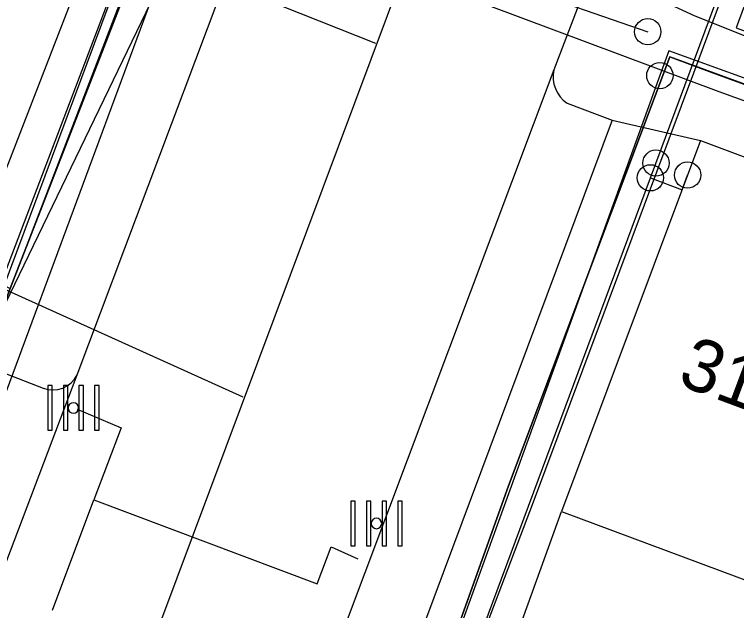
# Model space of a CAD drawing. Extents: x 192672 to 192910, y 446344 to 446512.
# Drawn here: x 192727.4 to 192741.13, y 446369.57 to 446380.91 of the extents above; entities that cross this region are included whole.
import ezdxf

# ---------------------------------------------------------------- set-up
doc = ezdxf.new("R2010")
doc.units = 0
for name, color, linetype in [('( Toegevoegd 29-11-2021 14_41_42) wegdeel vlak', 7, 'Continuous'), ('B-OI-KL-BUISLEIDING_OLIEGASCHEMICALIEN_GASLAGEDRUK-G', 7, 'Continuous'), ('B-OI-KL-DATA-G', 7, 'Continuous'), ('B-OI-KL-DATA_GTWP-S', 7, 'Continuous'), ('B-OI-KL-DATA_KABELBED-G', 7, 'Continuous'), ('B-OI-KL-DATA_MOF-S', 7, 'Continuous'), ('B-OI-KL-ET_LS-G', 7, 'Continuous'), ('B-OI-KL-GAS_LD_EINDKAP-S', 7, 'Continuous'), ('B-OI-KL-GAS_LD_OVERGANGSSTUK-S', 7, 'Continuous'), ('B-OI-KL-WATER-G', 7, 'Continuous'), ('B-OI-RI-RIOOLVRIJVERVAL-G', 7, 'Continuous'), ('Default', 7, 'Continuous'), ('huisnummerreeks BGT', 7, 'Continuous'), ('kant open verharding', 7, 'Continuous'), ('kant verharding', 7, 'Continuous'), ('kolk', 7, 'Continuous'), ('pand op maaiveld vlak', 7, 'Continuous')]:
    doc.layers.add(name, color=color, linetype=linetype)

# ---------------------------------------------------------------- blocks, each defined once
blk = doc.blocks.new('B-OI-KL-GAS_LD_EINDKAP-S')
at = {"layer": 'Default'}
blk.add_circle((0, 0), 0.25, dxfattribs=at)
blk = doc.blocks.new('B-OI-KL-GAS_LD_OVERGANGSSTUK-S')
at = {"layer": 'Default'}
blk.add_circle((0, 0), 0.25, dxfattribs=at)
blk = doc.blocks.new('B-OI-KL-DATA_GTWP-S')
at = {"layer": 'Default'}
blk.add_circle((0, 0), 0.25, dxfattribs=at)
blk = doc.blocks.new('B-OI-KL-DATA_MOF-S')
at = {"layer": 'Default'}
blk.add_circle((0, 0), 0.25, dxfattribs=at)

msp = doc.modelspace()

# ---------------------------------------------------------------- linework, layer by layer
at = {"layer": '( Toegevoegd 29-11-2021 14_41_42) wegdeel vlak'}
for p, q in [((192741.229, 446389.304), (192737.657, 446379.855)), ((192738.766, 446378.901), (192740.444, 446378.51)), ((192734.872, 446363.349), (192737.803, 446371.456))]:
    msp.add_line(p, q, dxfattribs=at)
msp.add_lwpolyline([(192744.875, 446390.822), (192741.123, 446380.652), (192757.478, 446374.617), (192757.644, 446375.067)], dxfattribs=at)
at = {"layer": 'B-OI-KL-BUISLEIDING_OLIEGASCHEMICALIEN_GASLAGEDRUK-G'}
for points in [[(192716.663, 446345.556), (192724.878, 446367.369), (192730.944, 446383.739), (192732.424, 446387.662), (192733.825, 446391.479)], [(192731.739, 446383.247), (192739.441, 446380.581)], [(192742.155, 446379.378), (192739.841, 446380.217), (192739.671, 446379.747)], [(192739.671, 446379.747), (192730.49, 446354.362), (192728.26, 446348.959), (192726.987, 446345.556)]]:
    msp.add_lwpolyline(points, dxfattribs=at)
at = {"layer": 'B-OI-KL-DATA-G'}
for points in [[(192768.74, 446486.807), (192749.794, 446435.599), (192742.072, 446415.039), (192739.06, 446406.841), (192738.917, 446406.249), (192738.75, 446405.758), (192738.438, 446405.088), (192738.002, 446404.406), (192737.543, 446403.858), (192737.067, 446403.408), (192736.56, 446403.025), (192736.06, 446402.723), (192733.684, 446396.245), (192734.518, 446394.712), (192730.316, 446383.423), (192727.316, 446375.697), (192722.899, 446364.033), (192722.458, 446362.715), (192718.077, 446351.086), (192716.68, 446347.404), (192715.968, 446345.556)], [(192768.74, 446486.807), (192749.794, 446435.599), (192742.072, 446415.039), (192739.06, 446406.841), (192738.917, 446406.249), (192738.75, 446405.758), (192738.438, 446405.088), (192738.002, 446404.406), (192737.543, 446403.858), (192737.067, 446403.408), (192736.56, 446403.025), (192736.06, 446402.723), (192733.684, 446396.245), (192734.518, 446394.712), (192730.316, 446383.423), (192727.316, 446375.697), (192722.899, 446364.033), (192722.458, 446362.715), (192718.077, 446351.086), (192716.68, 446347.404), (192715.968, 446345.556)], [(192768.74, 446486.807), (192749.794, 446435.599), (192742.072, 446415.039), (192739.06, 446406.841), (192738.917, 446406.249), (192738.75, 446405.758), (192738.438, 446405.088), (192738.002, 446404.406), (192737.543, 446403.858), (192737.067, 446403.408), (192736.56, 446403.025), (192736.06, 446402.723), (192733.684, 446396.245), (192734.518, 446394.712), (192730.316, 446383.423), (192727.316, 446375.697), (192722.899, 446364.033), (192722.458, 446362.715), (192718.077, 446351.086), (192716.68, 446347.404), (192715.968, 446345.556)], [(192768.74, 446486.807), (192749.794, 446435.599), (192742.072, 446415.039), (192739.06, 446406.841), (192738.917, 446406.249), (192738.75, 446405.758), (192738.438, 446405.088), (192738.002, 446404.406), (192737.543, 446403.858), (192737.067, 446403.408), (192736.56, 446403.025), (192736.06, 446402.723), (192733.684, 446396.245), (192734.518, 446394.712), (192730.316, 446383.423), (192727.316, 446375.697), (192722.899, 446364.033), (192722.458, 446362.715), (192718.077, 446351.086), (192716.68, 446347.404), (192715.968, 446345.556)], [(192768.74, 446486.807), (192749.794, 446435.599), (192742.072, 446415.039), (192739.06, 446406.841), (192738.917, 446406.249), (192738.75, 446405.758), (192738.438, 446405.088), (192738.002, 446404.406), (192737.543, 446403.858), (192737.067, 446403.408), (192736.56, 446403.025), (192736.06, 446402.723), (192733.684, 446396.245), (192734.518, 446394.712), (192730.316, 446383.423), (192727.316, 446375.697), (192722.899, 446364.033), (192722.458, 446362.715), (192718.077, 446351.086), (192716.68, 446347.404), (192715.968, 446345.556)], [(192768.74, 446486.807), (192749.794, 446435.599), (192742.072, 446415.039), (192739.06, 446406.841), (192738.917, 446406.249), (192738.75, 446405.758), (192738.438, 446405.088), (192738.002, 446404.406), (192737.543, 446403.858), (192737.067, 446403.408), (192736.56, 446403.025), (192736.06, 446402.723), (192733.684, 446396.245), (192734.518, 446394.712), (192730.316, 446383.423), (192727.316, 446375.697), (192722.899, 446364.033), (192722.458, 446362.715), (192718.077, 446351.086), (192716.68, 446347.404), (192715.968, 446345.556)], [(192768.74, 446486.807), (192749.794, 446435.599), (192742.072, 446415.039), (192739.06, 446406.841), (192738.917, 446406.249), (192738.75, 446405.758), (192738.438, 446405.088), (192738.002, 446404.406), (192737.543, 446403.858), (192737.067, 446403.408), (192736.56, 446403.025), (192736.06, 446402.723), (192733.684, 446396.245), (192734.518, 446394.712), (192730.316, 446383.423), (192727.316, 446375.697), (192722.899, 446364.033), (192722.458, 446362.715), (192718.077, 446351.086), (192716.68, 446347.404), (192715.968, 446345.556)], [(192768.74, 446486.807), (192749.794, 446435.599), (192742.072, 446415.039), (192739.06, 446406.841), (192738.917, 446406.249), (192738.75, 446405.758), (192738.438, 446405.088), (192738.002, 446404.406), (192737.543, 446403.858), (192737.067, 446403.408), (192736.56, 446403.025), (192736.06, 446402.723), (192733.684, 446396.245), (192734.518, 446394.712), (192730.316, 446383.423), (192727.316, 446375.697), (192722.899, 446364.033), (192722.458, 446362.715), (192718.077, 446351.086), (192716.68, 446347.404), (192715.968, 446345.556)], [(192768.74, 446486.807), (192749.794, 446435.599), (192742.072, 446415.039), (192739.06, 446406.841), (192738.917, 446406.249), (192738.75, 446405.758), (192738.438, 446405.088), (192738.002, 446404.406), (192737.543, 446403.858), (192737.067, 446403.408), (192736.56, 446403.025), (192736.06, 446402.723), (192733.684, 446396.245), (192734.518, 446394.712), (192730.316, 446383.423), (192727.316, 446375.697), (192722.899, 446364.033), (192722.458, 446362.715), (192718.077, 446351.086), (192716.68, 446347.404), (192715.968, 446345.556)], [(192768.74, 446486.807), (192749.794, 446435.599), (192742.072, 446415.039), (192739.06, 446406.841), (192738.917, 446406.249), (192738.75, 446405.758), (192738.438, 446405.088), (192738.002, 446404.406), (192737.543, 446403.858), (192737.067, 446403.408), (192736.56, 446403.025), (192736.06, 446402.723), (192733.684, 446396.245), (192734.518, 446394.712), (192730.316, 446383.423), (192727.316, 446375.697), (192722.899, 446364.033), (192722.458, 446362.715), (192718.077, 446351.086), (192716.68, 446347.404), (192715.968, 446345.556)], [(192768.74, 446486.807), (192749.794, 446435.599), (192742.072, 446415.039), (192739.06, 446406.841), (192738.917, 446406.249), (192738.75, 446405.758), (192738.438, 446405.088), (192738.002, 446404.406), (192737.543, 446403.858), (192737.067, 446403.408), (192736.56, 446403.025), (192736.06, 446402.723), (192733.684, 446396.245), (192734.518, 446394.712), (192730.316, 446383.423), (192727.316, 446375.697), (192722.899, 446364.033), (192722.458, 446362.715), (192718.077, 446351.086), (192716.68, 446347.404), (192715.968, 446345.556)], [(192768.74, 446486.807), (192749.794, 446435.599), (192742.072, 446415.039), (192739.06, 446406.841), (192738.917, 446406.249), (192738.75, 446405.758), (192738.438, 446405.088), (192738.002, 446404.406), (192737.543, 446403.858), (192737.067, 446403.408), (192736.56, 446403.025), (192736.06, 446402.723), (192733.684, 446396.245), (192734.518, 446394.712), (192730.316, 446383.423), (192727.316, 446375.697), (192722.899, 446364.033), (192722.458, 446362.715), (192718.077, 446351.086), (192716.68, 446347.404), (192715.968, 446345.556)], [(192768.74, 446486.807), (192749.794, 446435.599), (192742.072, 446415.039), (192739.06, 446406.841), (192738.917, 446406.249), (192738.75, 446405.758), (192738.438, 446405.088), (192738.002, 446404.406), (192737.543, 446403.858), (192737.067, 446403.408), (192736.56, 446403.025), (192736.06, 446402.723), (192733.684, 446396.245), (192734.518, 446394.712), (192730.316, 446383.423), (192727.316, 446375.697), (192722.899, 446364.033), (192722.458, 446362.715), (192718.077, 446351.086), (192716.68, 446347.404), (192715.968, 446345.556)], [(192768.74, 446486.807), (192749.794, 446435.599), (192742.072, 446415.039), (192739.06, 446406.841), (192738.917, 446406.249), (192738.75, 446405.758), (192738.438, 446405.088), (192738.002, 446404.406), (192737.543, 446403.858), (192737.067, 446403.408), (192736.56, 446403.025), (192736.06, 446402.723), (192733.684, 446396.245), (192734.518, 446394.712), (192730.316, 446383.423), (192727.316, 446375.697), (192722.899, 446364.033), (192722.458, 446362.715), (192718.077, 446351.086), (192716.68, 446347.404), (192715.968, 446345.556)], [(192768.74, 446486.807), (192749.794, 446435.599), (192742.072, 446415.039), (192739.06, 446406.841), (192738.917, 446406.249), (192738.75, 446405.758), (192738.438, 446405.088), (192738.002, 446404.406), (192737.543, 446403.858), (192737.067, 446403.408), (192736.56, 446403.025), (192736.06, 446402.723), (192733.684, 446396.245), (192734.518, 446394.712), (192730.316, 446383.423), (192727.316, 446375.697), (192722.899, 446364.033), (192722.458, 446362.715), (192718.077, 446351.086), (192716.68, 446347.404), (192715.968, 446345.556)], [(192675.743, 446430.156), (192678.122, 446429.261), (192683.193, 446427.673), (192696.077, 446422.823), (192719.012, 446414.118), (192720.2, 446413.77), (192739.06, 446406.841), (192738.917, 446406.249), (192738.75, 446405.758), (192738.438, 446405.088), (192738.002, 446404.406), (192737.543, 446403.858), (192737.067, 446403.408), (192736.56, 446403.025), (192736.06, 446402.723), (192733.684, 446396.245), (192734.518, 446394.712), (192730.316, 446383.423), (192727.316, 446375.697), (192722.899, 446364.033), (192722.458, 446362.715), (192718.077, 446351.086), (192716.68, 446347.404), (192715.968, 446345.556)], [(192675.743, 446430.156), (192678.122, 446429.261), (192683.193, 446427.673), (192696.077, 446422.823), (192719.012, 446414.118), (192720.2, 446413.77), (192739.06, 446406.841), (192738.917, 446406.249), (192738.75, 446405.758), (192738.438, 446405.088), (192738.002, 446404.406), (192737.543, 446403.858), (192737.067, 446403.408), (192736.56, 446403.025), (192736.06, 446402.723), (192733.684, 446396.245), (192734.518, 446394.712), (192730.316, 446383.423), (192727.316, 446375.697), (192722.899, 446364.033), (192722.458, 446362.715), (192718.077, 446351.086), (192716.68, 446347.404), (192715.968, 446345.556)], [(192675.743, 446430.156), (192678.122, 446429.261), (192683.193, 446427.673), (192696.077, 446422.823), (192719.012, 446414.118), (192720.2, 446413.77), (192739.06, 446406.841), (192738.917, 446406.249), (192738.75, 446405.758), (192738.438, 446405.088), (192738.002, 446404.406), (192737.543, 446403.858), (192737.067, 446403.408), (192736.56, 446403.025), (192736.06, 446402.723), (192733.684, 446396.245), (192734.518, 446394.712), (192730.316, 446383.423), (192727.316, 446375.697), (192722.899, 446364.033), (192722.458, 446362.715), (192718.077, 446351.086), (192716.68, 446347.404), (192715.968, 446345.556)], [(192675.743, 446430.156), (192678.122, 446429.261), (192683.193, 446427.673), (192696.077, 446422.823), (192719.012, 446414.118), (192720.2, 446413.77), (192739.06, 446406.841), (192738.917, 446406.249), (192738.75, 446405.758), (192738.438, 446405.088), (192738.002, 446404.406), (192737.543, 446403.858), (192737.067, 446403.408), (192736.56, 446403.025), (192736.06, 446402.723), (192733.684, 446396.245), (192734.518, 446394.712), (192730.316, 446383.423), (192727.316, 446375.697), (192722.899, 446364.033), (192722.458, 446362.715), (192718.077, 446351.086), (192716.68, 446347.404), (192715.968, 446345.556)], [(192675.743, 446430.156), (192678.122, 446429.261), (192683.193, 446427.673), (192696.077, 446422.823), (192719.012, 446414.118), (192720.2, 446413.77), (192739.06, 446406.841), (192738.917, 446406.249), (192738.75, 446405.758), (192738.438, 446405.088), (192738.002, 446404.406), (192737.543, 446403.858), (192737.067, 446403.408), (192736.56, 446403.025), (192736.06, 446402.723), (192733.684, 446396.245), (192734.518, 446394.712), (192730.316, 446383.423), (192727.316, 446375.697), (192722.899, 446364.033), (192722.458, 446362.715), (192718.077, 446351.086), (192716.68, 446347.404), (192715.968, 446345.556)], [(192675.743, 446430.156), (192678.122, 446429.261), (192683.193, 446427.673), (192696.077, 446422.823), (192719.012, 446414.118), (192720.2, 446413.77), (192739.06, 446406.841), (192738.917, 446406.249), (192738.75, 446405.758), (192738.438, 446405.088), (192738.002, 446404.406), (192737.543, 446403.858), (192737.067, 446403.408), (192736.56, 446403.025), (192736.06, 446402.723), (192733.684, 446396.245), (192734.518, 446394.712), (192730.316, 446383.423), (192727.316, 446375.697), (192722.899, 446364.033), (192722.458, 446362.715), (192718.077, 446351.086), (192716.68, 446347.404), (192715.968, 446345.556)], [(192715.968, 446345.556), (192716.68, 446347.404), (192718.077, 446351.086), (192722.458, 446362.715), (192722.899, 446364.033), (192727.316, 446375.697), (192730.316, 446383.423), (192734.518, 446394.712), (192733.684, 446396.245), (192736.06, 446402.723), (192736.56, 446403.025), (192737.067, 446403.408), (192737.543, 446403.858), (192738.002, 446404.406), (192738.438, 446405.088), (192738.75, 446405.758), (192738.917, 446406.249), (192739.06, 446406.841), (192720.2, 446413.77), (192719.012, 446414.118), (192698.154, 446422.035)], [(192715.968, 446345.556), (192716.68, 446347.404), (192718.077, 446351.086), (192722.458, 446362.715), (192722.899, 446364.033), (192727.316, 446375.697), (192730.316, 446383.423), (192734.518, 446394.712), (192733.684, 446396.245), (192736.06, 446402.723), (192736.56, 446403.025), (192737.067, 446403.408), (192737.543, 446403.858), (192738.002, 446404.406), (192738.438, 446405.088), (192738.75, 446405.758), (192738.917, 446406.249), (192739.06, 446406.841), (192720.2, 446413.77), (192719.012, 446414.118), (192703.056, 446420.174)], [(192715.968, 446345.556), (192716.68, 446347.404), (192718.077, 446351.086), (192722.458, 446362.715), (192722.899, 446364.033), (192727.316, 446375.697), (192730.316, 446383.423), (192734.518, 446394.712), (192733.684, 446396.245), (192736.06, 446402.723), (192736.56, 446403.025), (192737.067, 446403.408), (192737.543, 446403.858), (192738.002, 446404.406), (192738.438, 446405.088), (192738.75, 446405.758), (192738.917, 446406.249), (192739.06, 446406.841), (192720.2, 446413.77), (192719.012, 446414.118), (192707.704, 446418.41)], [(192751.673, 446411.261), (192751.244, 446410.174), (192750.935, 446409.68), (192750.147, 446407.673), (192750.467, 446406.312), (192749.5, 446403.782), (192748.987, 446403.342), (192747.735, 446399.921), (192747.259, 446399.193), (192746.924, 446398.578), (192744.851, 446393.422), (192744.761, 446392.29), (192744.458, 446390.955), (192740.313, 446379.795), (192737.259, 446371.63), (192734.058, 446363.201), (192730.017, 446352.288), (192729.223, 446350.283), (192728.827, 446349.172), (192727.477, 446345.556)], [(192733.785, 446392.743), (192730.316, 446383.423), (192727.316, 446375.697), (192722.899, 446364.033), (192722.458, 446362.715), (192718.077, 446351.086), (192716.68, 446347.404), (192715.968, 446345.556)], [(192718.113, 446380.217), (192718.126, 446380.244), (192727.316, 446375.697), (192730.316, 446383.423), (192731.53, 446386.684), (192730.686, 446386.998)], [(192777.905, 446365.29), (192778.164, 446365.987), (192777.507, 446366.23), (192773.332, 446367.794), (192762.994, 446371.683), (192740.707, 446379.788), (192739.862, 446380.106), (192736.793, 446371.939), (192730.818, 446355.23), (192731.661, 446354.909)], [(192731.661, 446354.909), (192730.818, 446355.23), (192736.793, 446371.939), (192739.862, 446380.106), (192740.707, 446379.788), (192762.994, 446371.683), (192773.332, 446367.794), (192777.507, 446366.23), (192792.515, 446360.708), (192794.868, 446359.138), (192813.343, 446352.261), (192813.029, 446351.418), (192812.66, 446350.461), (192825.476, 446345.665), (192825.435, 446345.556)], [(192825.435, 446345.556), (192825.476, 446345.665), (192812.66, 446350.461), (192813.029, 446351.418), (192813.343, 446352.261), (192794.868, 446359.138), (192792.515, 446360.708), (192777.507, 446366.23), (192773.332, 446367.794), (192762.994, 446371.683), (192740.707, 446379.788), (192739.862, 446380.106), (192736.793, 446371.939), (192730.818, 446355.23), (192731.661, 446354.909)], [(192731.661, 446354.909), (192730.818, 446355.23), (192736.793, 446371.939), (192739.862, 446380.106), (192740.707, 446379.788), (192762.994, 446371.683), (192773.332, 446367.794), (192777.507, 446366.23), (192792.515, 446360.708), (192794.868, 446359.138), (192813.343, 446352.261), (192813.029, 446351.418), (192812.66, 446350.461), (192825.476, 446345.665), (192825.435, 446345.556)], [(192825.435, 446345.556), (192825.476, 446345.665), (192812.66, 446350.461), (192813.029, 446351.418), (192813.343, 446352.261), (192794.868, 446359.138), (192792.515, 446360.708), (192777.507, 446366.23), (192773.332, 446367.794), (192762.994, 446371.683), (192740.707, 446379.788), (192739.862, 446380.106), (192736.793, 446371.939), (192730.818, 446355.23), (192731.661, 446354.909)], [(192825.435, 446345.556), (192825.476, 446345.665), (192812.66, 446350.461), (192813.029, 446351.418), (192813.343, 446352.261), (192794.868, 446359.138), (192792.515, 446360.708), (192777.507, 446366.23), (192773.332, 446367.794), (192762.994, 446371.683), (192740.707, 446379.788), (192739.862, 446380.106), (192736.793, 446371.939), (192730.818, 446355.23), (192731.661, 446354.909)], [(192825.435, 446345.556), (192825.476, 446345.665), (192812.66, 446350.461), (192813.029, 446351.418), (192813.343, 446352.261), (192794.868, 446359.138), (192792.515, 446360.708), (192777.507, 446366.23), (192773.332, 446367.794), (192762.994, 446371.683), (192740.707, 446379.788), (192739.862, 446380.106), (192736.793, 446371.939), (192730.818, 446355.23), (192731.661, 446354.909)], [(192825.435, 446345.556), (192825.476, 446345.665), (192812.66, 446350.461), (192813.029, 446351.418), (192813.343, 446352.261), (192794.868, 446359.138), (192792.515, 446360.708), (192777.507, 446366.23), (192773.332, 446367.794), (192762.994, 446371.683), (192740.707, 446379.788), (192739.862, 446380.106), (192736.793, 446371.939), (192730.818, 446355.23), (192731.661, 446354.909)], [(192731.661, 446354.909), (192730.818, 446355.23), (192736.793, 446371.939), (192739.862, 446380.106), (192740.707, 446379.788), (192762.994, 446371.683), (192773.332, 446367.794), (192777.507, 446366.23), (192792.515, 446360.708), (192794.868, 446359.138), (192813.343, 446352.261), (192813.029, 446351.418), (192812.66, 446350.461), (192825.476, 446345.665), (192825.435, 446345.556)], [(192731.661, 446354.909), (192730.818, 446355.23), (192736.793, 446371.939), (192739.862, 446380.106), (192740.707, 446379.788), (192762.994, 446371.683), (192773.332, 446367.794), (192777.507, 446366.23), (192792.515, 446360.708), (192794.868, 446359.138), (192813.343, 446352.261), (192813.029, 446351.418), (192812.66, 446350.461), (192825.476, 446345.665), (192825.435, 446345.556)], [(192825.435, 446345.556), (192825.476, 446345.665), (192812.66, 446350.461), (192813.029, 446351.418), (192813.343, 446352.261), (192794.868, 446359.138), (192792.515, 446360.708), (192777.507, 446366.23), (192773.332, 446367.794), (192762.994, 446371.683), (192740.707, 446379.788), (192739.862, 446380.106), (192736.793, 446371.939), (192730.818, 446355.23), (192731.661, 446354.909)], [(192825.435, 446345.556), (192825.476, 446345.665), (192812.66, 446350.461), (192813.029, 446351.418), (192813.343, 446352.261), (192794.868, 446359.138), (192792.515, 446360.708), (192777.507, 446366.23), (192773.332, 446367.794), (192762.994, 446371.683), (192740.707, 446379.788), (192739.862, 446380.106), (192736.793, 446371.939), (192730.818, 446355.23), (192731.661, 446354.909)], [(192777.905, 446365.29), (192778.164, 446365.987), (192777.507, 446366.23), (192773.332, 446367.794), (192762.994, 446371.683), (192740.707, 446379.788), (192739.862, 446380.106), (192736.793, 446371.939), (192732.637, 446360.318), (192733.582, 446359.958)]]:
    msp.add_lwpolyline(points, dxfattribs=at)
at = {"layer": 'B-OI-KL-DATA_KABELBED-G'}
for points in [[(192715.778, 446345.556), (192717.157, 446349.216), (192720.197, 446357.284), (192722.27, 446362.784), (192722.711, 446364.103), (192724.092, 446367.75), (192725.922, 446372.585), (192725.924, 446372.588), (192726.95, 446375.299), (192730.073, 446383.511), (192734.61, 446395.441)], [(192727.294, 446345.556), (192728.54, 446348.852), (192729.881, 446351.918), (192731.796, 446357.074), (192734.009, 446363.035), (192739.493, 446377.8), (192741.838, 446384.116), (192744.353, 446390.875), (192744.468, 446391.186)], [(192731.53, 446386.684), (192727.316, 446375.697)], [(192743.934, 446378.615), (192739.862, 446380.106), (192736.793, 446371.939), (192732.637, 446360.318)], [(192739.491, 446377.801), (192739.493, 446377.8), (192740.092, 446377.573), (192740.198, 446377.854)]]:
    msp.add_lwpolyline(points, dxfattribs=at)
at = {"layer": 'B-OI-KL-ET_LS-G'}
for points in [[(192716.073, 446345.556), (192727.138, 446375.229), (192730.971, 446383.179), (192732.504, 446387.295), (192732.765, 446387.575)], [(192812.885, 446353.609), (192808.475, 446355.248), (192804.025, 446356.797), (192795.126, 446359.954), (192777.441, 446366.051), (192758.408, 446373.136), (192745.69, 446378.74), (192740.34, 446380.878), (192731.982, 446384.732), (192732.765, 446387.575)]]:
    msp.add_lwpolyline(points, dxfattribs=at)
at = {"layer": 'B-OI-KL-WATER-G'}
for points in [[(192715.942, 446345.556), (192716.677, 446347.527), (192733.49, 446392.627), (192735.123, 446396.62)], [(192730.071, 446383.458), (192740.795, 446379.447), (192741.984, 446379.012), (192741.63, 446378.066)]]:
    msp.add_lwpolyline(points, dxfattribs=at)
at = {"layer": 'B-OI-RI-RIOOLVRIJVERVAL-G'}
for points in [[(192725.88, 446357.88), (192740.63, 446397.31)], [(192728.905, 446382.493), (192734.26, 446380.366)], [(192726.472, 446376.016), (192731.741, 446373.632)], [(192728.586, 446373.398), (192729.425, 446373.046), (192728.906, 446371.673), (192733.153, 446370.077), (192733.419, 446370.779), (192733.927, 446370.553)], [(192728.12, 446369.574), (192728.909, 446371.673)]]:
    msp.add_lwpolyline(points, dxfattribs=at)
at = {"layer": 'kant open verharding'}
for p, q in [((192728.589, 446374.052), (192734.543, 446389.88)), ((192729.467, 446383.724), (192726.296, 446375.548))]:
    msp.add_line(p, q, dxfattribs=at)
at = {"layer": 'kant verharding'}
for p, q in [((192737.657, 446379.855), (192731.919, 446364.598)), ((192737.908, 446379.221), (192738.766, 446378.901)), ((192724.36, 446362.912), (192728.589, 446374.052))]:
    msp.add_line(p, q, dxfattribs=at)
for points in [[(192738.766, 446378.901), (192733.402, 446364.531), (192732.55, 446364.886)], [(192724.074, 446363.455), (192723.221, 446363.769), (192727.106, 446374.125), (192727.941, 446373.798)]]:
    msp.add_lwpolyline(points, dxfattribs=at)
for centre, radius, start, end in [((192738.238, 446379.719), 0.597, 166.7906, 236.4065), ((192728.122, 446374.291), 0.525, 249.8498, 332.9581)]:
    msp.add_arc(centre, radius, start, end, dxfattribs=at)
at = {"layer": 'kolk'}
for points in [[(192728.113, 446373.423), (192728.113, 446373.848), (192728.028, 446373.848), (192728.028, 446373.423), (192728.028, 446372.998), (192728.113, 446372.998)], [(192728.411, 446373.423), (192728.411, 446373.848), (192728.326, 446373.848), (192728.326, 446373.423), (192728.326, 446372.998), (192728.411, 446372.998)], [(192728.708, 446373.423), (192728.708, 446373.848), (192728.623, 446373.848), (192728.623, 446373.423), (192728.623, 446372.998), (192728.708, 446372.998)], [(192729.006, 446373.423), (192729.006, 446373.848), (192728.921, 446373.848), (192728.921, 446373.423), (192728.921, 446372.998), (192729.006, 446372.998)], [(192733.877, 446371.226), (192733.877, 446371.651), (192733.792, 446371.651), (192733.792, 446371.226), (192733.792, 446370.801), (192733.877, 446370.801)], [(192734.175, 446371.226), (192734.175, 446371.651), (192734.09, 446371.651), (192734.09, 446371.226), (192734.09, 446370.801), (192734.175, 446370.801)], [(192734.472, 446371.226), (192734.472, 446371.651), (192734.387, 446371.651), (192734.387, 446371.226), (192734.387, 446370.801), (192734.472, 446370.801)], [(192734.77, 446371.226), (192734.77, 446371.651), (192734.685, 446371.651), (192734.685, 446371.226), (192734.685, 446370.801), (192734.77, 446370.801)]]:
    msp.add_lwpolyline(points, close=True, dxfattribs=at)
for centre, start, end in [((192728.517, 446373.423), 0, 180), ((192728.517, 446373.423), 180, 0), ((192734.281, 446371.226), 0, 180), ((192734.281, 446371.226), 180, 0)]:
    msp.add_arc(centre, 0.1, start, end, dxfattribs=at)
at = {"layer": 'pand op maaiveld vlak'}
for p, q in [((192740.444, 446378.51), (192737.803, 446371.456)), ((192740.444, 446378.51), (192744.876, 446376.852)), ((192737.803, 446371.456), (192742.235, 446369.796))]:
    msp.add_line(p, q, dxfattribs=at)

# ---------------------------------------------------------------- block references
at = {"layer": 'B-OI-KL-DATA_GTWP-S'}
for p in [(192739.491, 446377.801), (192740.198, 446377.854)]:
    msp.add_blockref('B-OI-KL-DATA_GTWP-S', p, dxfattribs=at)
at = {"layer": 'B-OI-KL-DATA_MOF-S'}
msp.add_blockref('B-OI-KL-DATA_MOF-S', (192739.597, 446378.082), dxfattribs=at)
at = {"layer": 'B-OI-KL-GAS_LD_EINDKAP-S'}
msp.add_blockref('B-OI-KL-GAS_LD_EINDKAP-S', (192739.441, 446380.581), dxfattribs=at)
at = {"layer": 'B-OI-KL-GAS_LD_OVERGANGSSTUK-S'}
msp.add_blockref('B-OI-KL-GAS_LD_OVERGANGSSTUK-S', (192739.671, 446379.747), dxfattribs=at)

# ---------------------------------------------------------------- texts
at = {"layer": 'huisnummerreeks BGT'}
msp.add_text('31', height=1, rotation=339.5, dxfattribs=at).set_placement((192739.979, 446373.88))

doc.saveas('drawing.dxf')
